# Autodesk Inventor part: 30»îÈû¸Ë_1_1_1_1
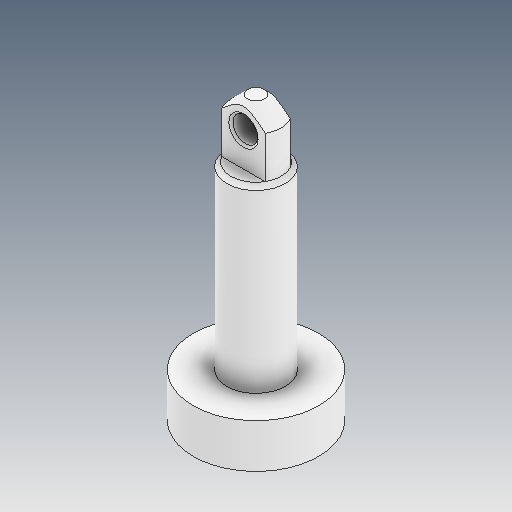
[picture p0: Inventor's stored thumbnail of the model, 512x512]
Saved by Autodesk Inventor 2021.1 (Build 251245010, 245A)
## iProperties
Created: 2021-05
Part Number: 30»îÈû¸Ë_1_1_1_1
Material: Ogólny
Document SubType Name: Modeling
Designer: user
Density: 1 g/cm^3
Appearance: Domyślna
Author: user
Revision Number: ÈÎºÎ
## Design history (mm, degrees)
feature "ÊäÈë1"
node "Bryła1"
